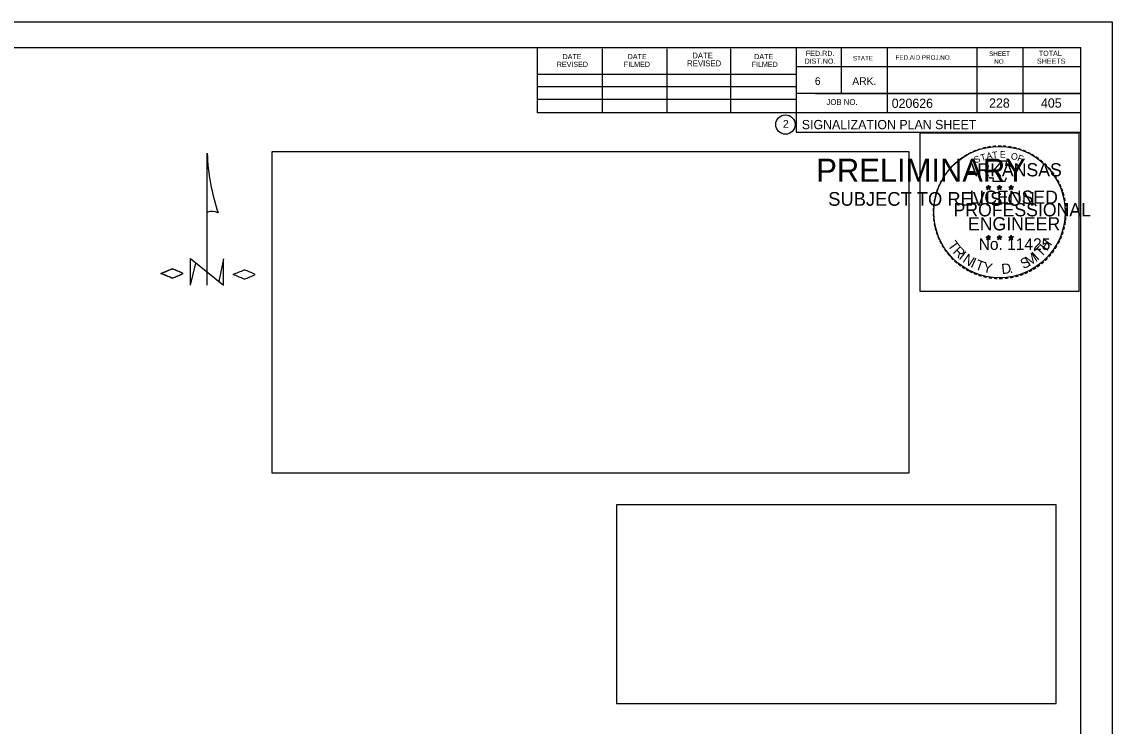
# Model space of a CAD drawing. Extents: x 1281646 to 1282646, y 1891886 to 1892526.
# Drawn here: x 1282151 to 1282646.3, y 1892206.5 to 1892526.5 of the extents above; entities that cross this region are included whole.
import ezdxf

# ---------------------------------------------------------------- set-up
doc = ezdxf.new("R2010")
doc.units = 0
for name, color, linetype in [('Default', 7, 'Continuous'), ('R_Border', 7, 'Continuous'), ('R_Border PE', 7, 'Continuous'), ('R_Border Prem', 7, 'Continuous'), ('R_No Plot', 7, 'Continuous'), ('T_Drafting', 7, 'Continuous')]:
    doc.layers.add(name, color=color, linetype=linetype)

msp = doc.modelspace()

# ---------------------------------------------------------------- linework, layer by layer
at = {"layer": 'Default'}
for points in [[(1282264.51, 1892321.52), (1282554.01, 1892321.52), (1282554.01, 1892467.35), (1282264.51, 1892467.35)], [(1282421.15, 1892216.75), (1282620.81, 1892216.75), (1282620.81, 1892307.02), (1282421.15, 1892307.02)]]:
    msp.add_lwpolyline(points, close=True, dxfattribs=at)
at = {"layer": 'R_Border'}
for p, q in [((1281683.46, 1892514.79), (1282632, 1892514.79)), ((1282385.22, 1892485.15), (1282385.22, 1892514.79)), ((1282414.8, 1892485.15), (1282414.8, 1892514.19)), ((1282444.08, 1892485.15), (1282444.08, 1892514.19)), ((1282473.12, 1892485.15), (1282473.12, 1892514.19)), ((1282502.7, 1892514.79), (1282502.7, 1892476.39)), ((1282523.22, 1892514.79), (1282523.22, 1892493.97)), ((1282544.04, 1892514.79), (1282544.04, 1892485.15)), ((1282584.78, 1892514.79), (1282584.78, 1892485.15)), ((1282605.6, 1892514.79), (1282605.6, 1892485.15)), ((1282632, 1891898.41), (1282632, 1892514.79)), ((1282632, 1892505.97), (1282502.7, 1892505.97)), ((1282632, 1892506.03), (1282632, 1892506.03)), ((1282385.22, 1892502.73), (1282502.7, 1892502.73)), ((1282385.22, 1892497.15), (1282502.7, 1892497.15)), ((1282385.22, 1892485.15), (1282385.22, 1892491.33)), ((1282385.22, 1892491.33), (1282502.7, 1892491.33)), ((1282632, 1892493.97), (1282502.7, 1892493.97)), ((1282511.58, 1892493.97), (1282632, 1892493.97)), ((1282632, 1892485.15), (1282385.22, 1892485.15)), ((1282502.7, 1892476.39), (1282632, 1892476.39))]:
    msp.add_line(p, q, dxfattribs=at)
msp.add_circle((1282497.86, 1892479.79), 4.4, dxfattribs=at)
at = {"layer": 'R_Border PE'}
for p, q in [((1282588.99, 1892451.47), (1282590.03, 1892451.13)), ((1282588.99, 1892451.47), (1282589.74, 1892451.33)), ((1282588.99, 1892451.47), (1282589.7, 1892451.1)), ((1282589.38, 1892450.24), (1282590.03, 1892451.13)), ((1282589.38, 1892450.24), (1282589.76, 1892450.98)), ((1282589.38, 1892450.24), (1282590.03, 1892450.89)), ((1282590.03, 1892452.23), (1282589.91, 1892451.47)), ((1282590.03, 1892451.13), (1282590.03, 1892452.23)), ((1282590.03, 1892452.23), (1282590.18, 1892451.48)), ((1282591.07, 1892451.47), (1282590.03, 1892451.13)), ((1282590.67, 1892450.24), (1282590.03, 1892451.13)), ((1282590.67, 1892450.24), (1282590.03, 1892450.89)), ((1282591.07, 1892451.47), (1282590.22, 1892451.32)), ((1282590.67, 1892450.24), (1282590.26, 1892451.12)), ((1282591.07, 1892451.47), (1282590.46, 1892451.16)), ((1282594, 1892451.47), (1282595.04, 1892451.13)), ((1282594, 1892451.47), (1282594.75, 1892451.33)), ((1282594, 1892451.47), (1282594.71, 1892451.1)), ((1282594.39, 1892450.24), (1282595.04, 1892451.13)), ((1282594.39, 1892450.24), (1282594.77, 1892450.98)), ((1282594.39, 1892450.24), (1282595.04, 1892450.89)), ((1282595.04, 1892452.23), (1282594.92, 1892451.47)), ((1282595.04, 1892451.13), (1282595.04, 1892452.23)), ((1282595.04, 1892452.23), (1282595.19, 1892451.48)), ((1282596.08, 1892451.47), (1282595.04, 1892451.13)), ((1282595.68, 1892450.24), (1282595.04, 1892451.13)), ((1282595.68, 1892450.24), (1282595.04, 1892450.89)), ((1282596.08, 1892451.47), (1282595.23, 1892451.32)), ((1282595.68, 1892450.24), (1282595.27, 1892451.12)), ((1282596.08, 1892451.47), (1282595.47, 1892451.16)), ((1282599.29, 1892451.43), (1282600.33, 1892451.1)), ((1282599.29, 1892451.43), (1282600.05, 1892451.3)), ((1282599.29, 1892451.43), (1282600, 1892451.07)), ((1282599.69, 1892450.21), (1282600.33, 1892451.1)), ((1282599.69, 1892450.21), (1282600.06, 1892450.94)), ((1282599.69, 1892450.21), (1282600.33, 1892450.86)), ((1282600.33, 1892452.19), (1282600.21, 1892451.44)), ((1282600.33, 1892451.1), (1282600.33, 1892452.19)), ((1282600.33, 1892452.19), (1282600.48, 1892451.44)), ((1282601.38, 1892451.43), (1282600.33, 1892451.1)), ((1282600.97, 1892450.21), (1282600.33, 1892451.1)), ((1282600.97, 1892450.21), (1282600.33, 1892450.85)), ((1282601.38, 1892451.43), (1282600.52, 1892451.28)), ((1282600.97, 1892450.21), (1282600.56, 1892451.08)), ((1282601.38, 1892451.43), (1282600.76, 1892451.13)), ((1282588.97, 1892428.75), (1282590.02, 1892428.42)), ((1282588.97, 1892428.75), (1282589.73, 1892428.61)), ((1282588.97, 1892428.75), (1282589.68, 1892428.38)), ((1282589.37, 1892427.52), (1282590.02, 1892428.42)), ((1282589.37, 1892427.52), (1282589.75, 1892428.26)), ((1282589.37, 1892427.52), (1282590.01, 1892428.18)), ((1282590.02, 1892429.51), (1282589.9, 1892428.75)), ((1282590.66, 1892427.52), (1282590.01, 1892428.17)), ((1282590.02, 1892428.42), (1282590.02, 1892429.51)), ((1282590.02, 1892429.51), (1282590.17, 1892428.76)), ((1282591.06, 1892428.75), (1282590.02, 1892428.42)), ((1282590.66, 1892427.52), (1282590.02, 1892428.42)), ((1282591.06, 1892428.75), (1282590.2, 1892428.6)), ((1282590.66, 1892427.52), (1282590.25, 1892428.4)), ((1282591.06, 1892428.75), (1282590.45, 1892428.44)), ((1282593.98, 1892428.75), (1282595.03, 1892428.42)), ((1282593.98, 1892428.75), (1282594.74, 1892428.61)), ((1282593.98, 1892428.75), (1282594.69, 1892428.38)), ((1282594.38, 1892427.52), (1282595.03, 1892428.42)), ((1282594.38, 1892427.52), (1282594.76, 1892428.26)), ((1282594.38, 1892427.52), (1282595.02, 1892428.18)), ((1282595.03, 1892429.51), (1282594.9, 1892428.75)), ((1282595.67, 1892427.52), (1282595.02, 1892428.17)), ((1282595.03, 1892428.42), (1282595.03, 1892429.51)), ((1282595.03, 1892429.51), (1282595.17, 1892428.76)), ((1282596.07, 1892428.75), (1282595.03, 1892428.42)), ((1282595.67, 1892427.52), (1282595.03, 1892428.42)), ((1282596.07, 1892428.75), (1282595.21, 1892428.6)), ((1282595.67, 1892427.52), (1282595.26, 1892428.4)), ((1282596.07, 1892428.75), (1282595.46, 1892428.44)), ((1282599.28, 1892428.72), (1282600.33, 1892428.39)), ((1282599.28, 1892428.72), (1282600.04, 1892428.58)), ((1282599.28, 1892428.72), (1282599.99, 1892428.35)), ((1282599.68, 1892427.49), (1282600.33, 1892428.39)), ((1282599.68, 1892427.49), (1282600.06, 1892428.23)), ((1282599.68, 1892427.49), (1282600.32, 1892428.15)), ((1282600.33, 1892429.48), (1282600.21, 1892428.72)), ((1282600.97, 1892427.49), (1282600.32, 1892428.14)), ((1282600.33, 1892428.39), (1282600.33, 1892429.48)), ((1282600.33, 1892429.48), (1282600.48, 1892428.73)), ((1282601.37, 1892428.72), (1282600.33, 1892428.39)), ((1282600.97, 1892427.49), (1282600.33, 1892428.39)), ((1282601.37, 1892428.72), (1282600.51, 1892428.57)), ((1282600.97, 1892427.49), (1282600.56, 1892428.37)), ((1282601.37, 1892428.72), (1282600.76, 1892428.41))]:
    msp.add_line(p, q, dxfattribs=at)
for points in [[(1282589.11, 1892463.1), (1282589.92, 1892460.62)], [(1282599.64, 1892460.34), (1282600.07, 1892461.19), (1282598.01, 1892461.12), (1282598.46, 1892463.1), (1282589.11, 1892463.1)], [(1282590.58, 1892455.83), (1282590.58, 1892455.57), (1282592.27, 1892455.51), (1282592.11, 1892454.1), (1282597.72, 1892454.1), (1282598.32, 1892455.7)], [(1282590.03, 1892452.23), (1282590.67, 1892450.24), (1282588.99, 1892451.47), (1282591.07, 1892451.47), (1282589.38, 1892450.24), (1282590.03, 1892452.23)], [(1282595.04, 1892452.23), (1282595.68, 1892450.24), (1282594, 1892451.47), (1282596.08, 1892451.47), (1282594.39, 1892450.24), (1282595.04, 1892452.23)], [(1282600.33, 1892452.19), (1282600.97, 1892450.21), (1282599.29, 1892451.43), (1282601.38, 1892451.43), (1282599.69, 1892450.21), (1282600.33, 1892452.19)], [(1282590.02, 1892429.51), (1282590.66, 1892427.52), (1282588.97, 1892428.75), (1282591.06, 1892428.75), (1282589.37, 1892427.52), (1282590.02, 1892429.51)], [(1282595.03, 1892429.51), (1282595.67, 1892427.52), (1282593.98, 1892428.75), (1282596.07, 1892428.75), (1282594.38, 1892427.52), (1282595.03, 1892429.51)], [(1282600.33, 1892429.48), (1282600.97, 1892427.49), (1282599.28, 1892428.72), (1282601.37, 1892428.72), (1282599.68, 1892427.49), (1282600.33, 1892429.48)]]:
    msp.add_lwpolyline(points, dxfattribs=at)
for centre, radius in [((1282590.03, 1892451.13), 0.517), ((1282590.03, 1892451.13), 0.434), ((1282590.03, 1892451.13), 0.347), ((1282590.03, 1892451.13), 0.297), ((1282590.03, 1892451.13), 0.224), ((1282590.03, 1892451.13), 0.149), ((1282590.03, 1892451.13), 0.0889), ((1282595.04, 1892451.13), 0.517), ((1282595.04, 1892451.13), 0.434), ((1282595.04, 1892451.13), 0.347), ((1282595.04, 1892451.13), 0.297), ((1282595.04, 1892451.13), 0.224), ((1282595.04, 1892451.13), 0.149), ((1282595.04, 1892451.13), 0.0889), ((1282600.33, 1892451.1), 0.517), ((1282600.33, 1892451.1), 0.434), ((1282600.33, 1892451.1), 0.347), ((1282600.33, 1892451.1), 0.297), ((1282600.33, 1892451.1), 0.224), ((1282600.33, 1892451.1), 0.149), ((1282600.33, 1892451.1), 0.0889), ((1282590.02, 1892428.41), 0.517), ((1282590.02, 1892428.41), 0.434), ((1282590.02, 1892428.41), 0.347), ((1282590.02, 1892428.41), 0.297), ((1282590.02, 1892428.41), 0.224), ((1282590.02, 1892428.41), 0.149), ((1282590.02, 1892428.41), 0.0889), ((1282595.02, 1892428.41), 0.517), ((1282595.02, 1892428.41), 0.434), ((1282595.02, 1892428.41), 0.347), ((1282595.02, 1892428.41), 0.297), ((1282595.02, 1892428.41), 0.224), ((1282595.02, 1892428.41), 0.149), ((1282595.02, 1892428.41), 0.0889), ((1282600.33, 1892428.38), 0.517), ((1282600.33, 1892428.38), 0.434), ((1282600.33, 1892428.38), 0.347), ((1282600.33, 1892428.38), 0.297), ((1282600.33, 1892428.38), 0.224), ((1282600.33, 1892428.38), 0.149), ((1282600.33, 1892428.38), 0.0889)]:
    msp.add_circle(centre, radius, dxfattribs=at)
at = {"layer": 'R_No Plot'}
for p, q in [((1281646.26, 1892526.47), (1282646.26, 1892526.47)), ((1282558.83, 1892407.34), (1282558.83, 1892407.34))]:
    msp.add_line(p, q, dxfattribs=at)
for points in [[(1281646.24, 1892526.47), (1282646.26, 1892526.47), (1282646.26, 1891886.46), (1281646.24, 1891886.46)], [(1282559.07, 1892476.02), (1282631.07, 1892476.02), (1282631.07, 1892404.02), (1282559.07, 1892404.02)]]:
    msp.add_lwpolyline(points, close=True, dxfattribs=at)
msp.add_circle((1282595.07, 1892440.02), 29.86, dxfattribs=at)
at = {"layer": 'T_Drafting'}
for p, q in [((1282235.16, 1892406.76), (1282235.16, 1892466.74)), ((1282227.66, 1892406.79), (1282230.13, 1892416.82)), ((1282227.67, 1892406.76), (1282227.67, 1892418.96)), ((1282227.67, 1892418.96), (1282242.66, 1892406.76)), ((1282242.66, 1892418.73), (1282240.53, 1892408.53)), ((1282242.65, 1892418.71), (1282242.66, 1892418.73)), ((1282242.66, 1892406.76), (1282242.66, 1892418.73))]:
    msp.add_line(p, q, dxfattribs=at)
for centre, radius, start, end in [((1282332.96, 1892470.67), 97.82, 182.2815, 198.4669), ((1282237.52, 1892434.82), 5.53, 61.6986, 115.682), ((1282149.61, 1892576.14), 176.2, 291.4742, 293.2539), ((1282149.61, 1892248.14), 176.2, 66.7461, 68.5258), ((1282149.84, 1892576.14), 176.2, 291.4742, 293.2539), ((1282149.84, 1892248.14), 176.2, 66.7461, 68.5258), ((1282190.93, 1892340.57), 78.93, 65.1071, 68.9839), ((1282190.93, 1892483.7), 78.93, 291.0161, 294.8929), ((1282191.16, 1892340.57), 78.93, 65.1071, 68.9839), ((1282191.16, 1892483.7), 78.93, 291.0161, 294.8929), ((1282182.46, 1892575.67), 176.2, 291.4742, 293.2539), ((1282182.46, 1892247.68), 176.2, 66.7461, 68.5258), ((1282223.78, 1892340.11), 78.93, 65.1071, 68.9839), ((1282223.78, 1892483.24), 78.93, 291.0161, 294.8929)]:
    msp.add_arc(centre, radius, start, end, dxfattribs=at)

# ---------------------------------------------------------------- texts
at = {"layer": 'R_Border'}
for s, height, p in [('DATE', 2.346, (1282396.62, 1892509.51)), ('DATE', 2.346, (1282426.2, 1892509.51)), ('DATE', 2.638, (1282455.54, 1892509.81)), ('DATE', 2.346, (1282483.68, 1892509.51)), ('FED.RD.', 2.346, (1282507.14, 1892510.95)), ('STATE', 2.052, (1282528.5, 1892508.91)), ('FED.AID PROJ.NO.', 2.052, (1282547.88, 1892509.21)), ('SHEET', 2.052, (1282590.36, 1892510.95)), ('TOTAL', 2.346, (1282612.92, 1892510.95)), ('REVISED', 2.346, (1282393.98, 1892505.97)), ('FILMED', 2.346, (1282424.46, 1892505.97)), ('REVISED', 2.638, (1282453.2, 1892506.27)), ('FILMED', 2.346, (1282482.48, 1892505.97)), ('DIST.NO.', 2.346, (1282506.54, 1892507.41)), ('NO.', 2.052, (1282592.7, 1892507.41)), ('SHEETS', 2.346, (1282612.08, 1892507.41)), ('6', 3.52, (1282511.22, 1892497.75)), ('ARK.', 3.517, (1282528.2, 1892497.75)), ('JOB NO.', 2.638, (1282516.5, 1892488.69)), ('020626', 4.2, (1282546.13, 1892487.36)), ('228', 4.2, (1282590.34, 1892487.46)), ('405', 4.2, (1282613.91, 1892487.46)), ('2', 3.52, (1282496.72, 1892478.33)), ('SIGNALIZATION PLAN SHEET', 4.2, (1282505.29, 1892477.68))]:
    msp.add_text(s, height=height, dxfattribs=at).set_placement(p)
at = {"layer": 'R_Border PE'}
for s, height, rotation, p in [('-', 4.8, 5.8968, (1282591.82, 1892468.02)), ('-', 4.8, 0.1862, (1282594.14, 1892468.24)), ('-', 4.8, 357.743, (1282596.31, 1892468.2)), ('-', 4.8, 34.0636, (1282579.76, 1892463.61)), ('-', 4.8, 28.7918, (1282581.55, 1892464.72)), ('-', 4.8, 24.3072, (1282583.45, 1892465.68)), ('S', 3, 21.594, (1282584.17, 1892462.14)), ('-', 4.8, 19.1761, (1282585.35, 1892466.48)), ('T', 3, 16.4036, (1282586.92, 1892463.13)), ('-', 4.8, 13.6302, (1282587.6, 1892467.21)), ('A', 3, 11.2132, (1282589.39, 1892463.88)), ('-', 4.8, 10.2193, (1282589.64, 1892467.69)), ('T', 3, 6.0228, (1282591.94, 1892464.38)), ('E', 3, 0.8323, (1282595.26, 1892464.71)), ('-', 4.8, 352.1617, (1282598.54, 1892468.03)), ('O', 3, 350.4515, (1282600.07, 1892464.08)), ('-', 4.8, 347.2049, (1282600.7, 1892467.69)), ('F', 3, 340.0707, (1282602.93, 1892463.4)), ('-', 4.8, 342.3362, (1282602.6, 1892467.22)), ('-', 4.8, 337.8551, (1282604.81, 1892466.55)), ('-', 4.8, 334.1211, (1282606.7, 1892465.74)), ('-', 4.8, 329.6409, (1282608.44, 1892464.89)), ('-', 4.8, 325.8627, (1282610.37, 1892463.81)), ('-', 4.8, 48.4231, (1282573.96, 1892458.61)), ('-', 4.8, 42.9622, (1282575.3, 1892460.04)), ('-', 4.8, 38.9507, (1282576.6, 1892461.3)), ('-', 4.8, 36.2317, (1282578.03, 1892462.43)), ('-', 4.8, 320.5297, (1282612.2, 1892462.53)), ('-', 4.8, 315.5786, (1282613.99, 1892461.07)), ('-', 4.8, 309.8797, (1282615.7, 1892459.42)), ('-', 4.8, 58.0706, (1282570.53, 1892453.87)), ('-', 4.8, 54.2325, (1282571.51, 1892455.45)), ('-', 4.8, 50.6142, (1282572.75, 1892457.15)), ('-', 4.8, 306.6522, (1282617.28, 1892457.61)), ('-', 4.2, 303.6753, (1282618.73, 1892455.91)), ('-', 4.8, 72.3945, (1282568.16, 1892448.31)), ('-', 4.8, 67.7743, (1282568.82, 1892450.2)), ('-', 4.8, 62.8713, (1282569.59, 1892452.03)), ('-', 4.8, 299.6684, (1282619.69, 1892454.09)), ('-', 4.8, 294.6628, (1282620.66, 1892452.25)), ('-', 4.8, 290.5728, (1282621.43, 1892450.52)), ('-', 4.8, 81.2013, (1282567.17, 1892444.02)), ('-', 4.8, 75.461, (1282567.57, 1892446.16)), ('-', 4.8, 285.1233, (1282622.14, 1892448.78)), ('-', 4.8, 280.5493, (1282622.74, 1892446.55)), ('-', 4.8, 89.0622, (1282566.87, 1892439.85)), ('-', 4.8, 85.1863, (1282566.94, 1892441.95)), ('-', 4.8, 276.5962, (1282623.22, 1892444.25)), ('-', 4.8, 274.3301, (1282623.4, 1892442.08)), ('-', 4.8, 94.1959, (1282566.97, 1892437.67)), ('-', 4.8, 98.9479, (1282567.19, 1892435.67)), ('-', 4.8, 260.9953, (1282623.23, 1892436.23)), ('-', 4.8, 263.5172, (1282623.45, 1892438.19)), ('-', 4.8, 269.9407, (1282623.5, 1892440.19)), ('-', 4.8, 101.7149, (1282567.6, 1892433.47)), ('-', 4.8, 105.4578, (1282568.08, 1892431.69)), ('-', 4.8, 109.0874, (1282568.73, 1892429.8)), ('-', 4.8, 252.8681, (1282622.36, 1892432.03)), ('-', 4.8, 255.7626, (1282622.9, 1892434.19)), ('-', 4.8, 114.0643, (1282569.49, 1892428.01)), ('-', 4.8, 115.7289, (1282570.4, 1892426.15)), ('T', 4.62, 306.0406, (1282571.3, 1892424.93)), ('H', 4.62, 54.6088, (1282616.66, 1892422.04)), ('-', 4.8, 244.6197, (1282620.91, 1892428.13)), ('-', 4.8, 247.8887, (1282621.69, 1892430.01)), ('-', 4.8, 120.4471, (1282571.47, 1892424.4)), ('-', 4.8, 125.8934, (1282572.68, 1892422.71)), ('-', 4.8, 130.7181, (1282574.07, 1892421.06)), ('R', 4.62, 314.005, (1282573.59, 1892421.79)), ('I', 4.62, 321.9694, (1282576.29, 1892418.99)), ('N', 4.62, 326.5002, (1282577.99, 1892417.58)), ('M', 4.62, 32.6563, (1282608.45, 1892415.23)), ('I', 4.62, 42.1136, (1282612.31, 1892417.77)), ('T', 4.62, 46.6444, (1282613.99, 1892419.21)), ('-', 4.8, 231.2538, (1282617.23, 1892422.21)), ('-', 4.8, 233.8452, (1282618.52, 1892423.91)), ('-', 4.8, 239.0712, (1282619.72, 1892425.87)), ('-', 4.8, 134.2238, (1282575.62, 1892419.42)), ('-', 4.8, 138.9338, (1282577.2, 1892418.03)), ('-', 4.8, 144.6463, (1282578.86, 1892416.81)), ('I', 4.62, 335.3603, (1282581.61, 1892415.22)), ('T', 4.62, 339.8912, (1282583.6, 1892414.24)), ('Y', 4.62, 347.8556, (1282587.25, 1892412.9)), ('D', 4.62, 6.3969, (1282596.2, 1892411.82)), ('S', 4.62, 26.9312, (1282605.94, 1892414.02)), ('-', 4.8, 215.7363, (1282612.58, 1892417.58)), ('-', 4.8, 221.0851, (1282614.22, 1892419)), ('-', 4.8, 225.7653, (1282615.79, 1892420.52)), ('-', 4.8, 148.0898, (1282580.55, 1892415.7)), ('-', 4.8, 151.5704, (1282582.28, 1892414.72)), ('-', 4.8, 154.6002, (1282583.85, 1892413.98)), ('-', 4.8, 158.5612, (1282585.72, 1892413.22)), ('-', 4.8, 162.7983, (1282587.78, 1892412.58)), ('-', 4.8, 167.5555, (1282589.93, 1892412.09)), ('.', 4.62, 13.7642, (1282599.78, 1892412.21)), ('-', 4.8, 195.4743, (1282603.54, 1892412.88)), ('-', 4.8, 200.7184, (1282605.57, 1892413.6)), ('-', 4.8, 204.2516, (1282607.43, 1892414.42)), ('-', 4.8, 207.3568, (1282609.3, 1892415.38)), ('-', 4.8, 212.2491, (1282610.98, 1892416.42)), ('-', 4.8, 173.1155, (1282592.24, 1892411.76)), ('-', 4.8, 176.5183, (1282594.49, 1892411.6)), ('-', 4.8, 181.5918, (1282596.72, 1892411.66)), ('-', 4.8, 185.8167, (1282599.15, 1892411.89)), ('-', 4.8, 191.2858, (1282601.35, 1892412.28))]:
    msp.add_text(s, height=height, rotation=rotation, dxfattribs=at).set_placement(p)
for s, height, p in [('ARKANSAS', 6, (1282579.67, 1892456.24)), ('DWB', 0.03, (1282589.99, 1892451.12)), ('DWB', 0.03, (1282595, 1892451.12)), ('DWB', 0.03, (1282600.3, 1892451.09)), ('LICENSED', 6, (1282581.46, 1892443.79)), ('PROFESSIONAL', 6, (1282574.19, 1892438.08)), ('ENGINEER', 6, (1282580.75, 1892431.7)), ('No. 11425', 5.271, (1282585.63, 1892422.85)), ('DWB', 0.03, (1282589.98, 1892428.4)), ('DWB', 0.03, (1282594.99, 1892428.4)), ('DWB', 0.03, (1282600.29, 1892428.37))]:
    msp.add_text(s, height=height, dxfattribs=at).set_placement(p)
at = {"layer": 'R_Border Prem'}
for s, height, p in [('PRELIMINARY', 10.5, (1282511.86, 1892453.77)), ('SUBJECT TO REVISION', 6.2253, (1282517.28, 1892442.89))]:
    msp.add_text(s, height=height, dxfattribs=at).set_placement(p)

doc.saveas('drawing.dxf')
